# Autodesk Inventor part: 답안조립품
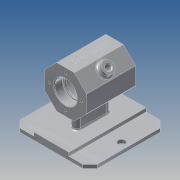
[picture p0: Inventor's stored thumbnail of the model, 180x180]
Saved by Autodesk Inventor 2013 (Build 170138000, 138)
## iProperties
Created: 2018-06
Part Number: 답안조립품
Material: 알루미늄 6061
Document SubType Name: Modeling
Designer: doa
Density: 2.71 g/cm^3
Mass: 554.043 g
Surface Area: 601.93 cm^2
Volume: 204.444 cm^3
Author: doa
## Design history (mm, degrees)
sketch "스케치2"
  geometry: L1 (30, -12.426)-(12.426, -30); L2 (12.426, -30)-(-12.426, -30); L3 (-12.426, -30)-(-30, -12.426); L4 (-30, -12.426)-(-30, 12.426); L5 (-30, 12.426)-(-12.426, 30); L6 (-12.426, 30)-(12.426, 30); L7 (12.426, 30)-(30, 12.426); L8 (30, 12.426)-(30, -12.426); 2 further points
  constraints: 16 end point, 1 coincident, 1 vertical, 17 other
  dimensions: "d7" = 60 distance between parallel lines of L6 L2
extrude "돌출1" new body sketch "스케치2" stored distance "d8" = 70; taper "d9" = 0 deg
sketch "스케치3"
  geometry: L1 (0, 35)-(0, -40.032); L2 (30, -35)-(-30, -35) reference; L3 (-30, -35)-(-30, 35) reference; L4 (-30, 35)-(30, 35) reference; L5 (30, 35)-(30, -35) reference; L6 (16, 35)-(16, 23); L7 (16, 23)-(14, 23); L8 (14, 23)-(14, 20); L9 (14, 20)-(25, 20); L10 (25, 20)-(25, -20); L11 (25, -20)-(14, -20); L12 (14, -20)-(14, -23); L13 (14, -23)-(16, -23); L14 (16, -23)-(16, -35); L15 (0, -35)-(16, -35); L16 (16, 35)-(0, 35); L17 (0, 35)-(0, -35); 1 further point
  constraints: 26 end point, 7 parallel, 3 perpendicular, 3 point on line, 2 collinear, 1 midpoint, 1 vertical
  dimensions: "d10" = 12 distance of L6.start L6.end; "d12" = 32 diameter of L6 L1; "d13" = 50 diameter of L10 L1; "d14" = 3 distance of L7.end L8.end; "d15" = 3 distance of L11.end L12.end; "d16" = 12 distance of L13.end L14.end; "d17" = 28 diameter of L8 L1; "d18" = 32 diameter of L14 L1; "d19" = 28 diameter of L12 L1
revolve "회전1" sketch "스케치3" stored, may be unused: angle "d20" = 90 deg
node "작업 평면1"
sketch "스케치5"
  geometry: L1 (-55, 55)-(55, 55); L2 (55, 55)-(55, -55); L3 (55, -55)-(-55, -55); L4 (-55, -55)-(-55, 55); 1 further point
  constraints: 8 end point, 2 parallel, 1 horizontal, 1 perpendicular
  dimensions: "d22" = 110 distance between parallel lines of L2 L4; "d24" = 110 distance between parallel lines of L3 L1; "d25" = 55 horizontal distance of L1.end point (0, 0); "d26" = 55 horizontal distance of L1.end point (0, 0)
extrude "돌출2" join sketch "스케치5" distance "d27" = 5; taper "d28" = 0 deg
sketch "스케치6"
  geometry: L1 (55, -55)-(55, 55) reference; L2 (55, -55)-(-55, -55) reference; L3 (-55, -55)-(-55, 55) reference; L4 (-55, 55)-(55, 55) reference; L5 (55, 55)-(55, -55) reference; L6 (55, -55)-(-55, -55) reference; L7 (-55, -55)-(-55, 55) reference; L8 (-55, 55)-(55, 55) reference; L9 (55, 55)-(55, -55) reference; L10 (-45, 55)-(-55, 45); L11 (-55, 55)-(-45, 55); L12 (-55, 55)-(-55, 45); L13 (45, 55)-(55, 55); L14 (55, 55)-(55, 45); L15 (55, 45)-(45, 55); L16 (45, -55)-(55, -45); L17 (55, -45)-(55, -55); L18 (55, -55)-(45, -55); L19 (-55, -55)-(-55, -45); L20 (-55, -45)-(-45, -55); L21 (-45, -55)-(-55, -55); 1 further point
  constraints: 24 end point, 8 point on line, 4 collinear, 3 perpendicular
  dimensions: "d29" = 10 distance of L3.end L10.end; "d30" = 10 distance of L3.end L10.start; "d31" = 10 distance of L2.end L19.end; "d32" = 10 distance of L20.end L2.end; "d33" = 10 distance of L1.start L16.start; "d34" = 10 distance of L16.end L1.start; "d35" = 10 distance of L1.end L13.start
extrude "돌출3" cut sketch "스케치6" stored distance "d36" = 5; taper "d37" = 0 deg
sketch "스케치7"
  geometry: L1 (-55, 45)-(-55, -45) reference; L2 (-45, -55)-(45, -55) reference; L3 (55, -45)-(55, 45) reference; L4 (45, 55)-(-45, 55) reference; L5 (25, 55)-(-25, 55); L6 (-25, 55)-(-25, -55); L7 (-25, -55)-(25, -55); L8 (25, -55)-(25, 55); 1 further point
  constraints: 8 end point, 2 parallel, 2 point on line, 1 horizontal, 1 perpendicular
  dimensions: "d38" = 30 distance between parallel lines of L3 L8; "d39" = 30 distance between parallel lines of L1 L6
extrude "돌출4" join sketch "스케치7" distance "d40" = 5; taper "d41" = 0 deg
sketch "스케치8"
  geometry: L1 (-25, 55)-(-25, -55) reference; L2 (5, 19)-(5, -19); L3 (-5, -19)-(-5, 19); A1 r 5 centre (0, 19) between (5, 19) and (-5, 19); A2 r 5 centre (0, -19) between (-5, -19) and (5, -19); 1 further point
  constraints: 4 end point, 4 point on circle, 3 tangent, 2 centre point, 2 vertical alignment, 1 equal radius, 1 parallel
  dimensions: "d42" = 10 diameter of A1; "d44" = 38 distance of A2.centre A1.centre; "d45" = 19 distance of point (0, 0) A1.centre
extrude "돌출5" join sketch "스케치8" stored distance "d46" = 5; taper "d47" = 0 deg
sketch "스케치9"
  geometry: L1 (0, 0)-(0, 70) reference; L2 (-24.853, 70)-(0, 70) reference; L3 (-24.853, 70)-(-24.853, 0) reference; L4 (0, 0)-(-24.853, 0) reference; L5 (-24.853, 35)-(0, 35); L6 (-12.426, 70)-(-12.426, 0); C1 r 8 at (-12.426, 35); 1 further point
  constraints: 4 end point, 4 midpoint, 1 centre point, 1 coincident
  dimensions: "d51" = 16 diameter of C1
extrude "돌출6" join sketch "스케치9" distance "d53" = 7; taper "d54" = 0 deg
sketch "스케치10"
  geometry: C1 r 8 at (0, 0) reference; C2 r 4 at (0, 0)
  constraints: 1 centre point, 1 coincident
  dimensions: "d55" = 8 diameter of C2
extrude "돌출7" cut sketch "스케치10" stored distance "d57" = 7; taper "d58" = 0 deg
fillet "모깎기1" dims "d59" = 1
sketch "스케치11"
  geometry: C1 r 16 at (0, 0) reference; A1 r 23 centre (0, 0) between (-23, 0) and (23, 0); 2 further points
  constraints: 4 point on circle, 2 horizontal alignment, 2 vertical alignment, 1 centre point, 1 coincident
  dimensions: "d60" = 46 diameter of A1
hole "구멍1" sketch "스케치11" at (-23, 0), (23, 0), (0, 23), (0, -23) diameter "d62" = 3.242; stored, may be unused: countersink angle "d66" = 90 deg, drill point angle "d68" = 118 deg; dims "d63" = 8, "d64" = 4, "d65" = 2, "d67" = 10
sketch "스케치12"
  geometry: L1 (-25, 55)-(-45, 55) reference; L2 (-55, 45)-(-55, -45) reference; C1 r 5 at (-45, 0); 1 further point
  constraints: 1 centre point
  dimensions: "d69" = 55 distance from line of C1.centre L1; "d70" = 10 distance from line of L2 C1.centre; "d71" = 10 diameter of C1
extrude "돌출8" cut sketch "스케치12" stored distance "d72" = 7; taper "d73" = 0 deg
fillet "모깎기2" dims "d74" = 2
fillet "모깎기3" dims "d75" = 3
fillet "모깎기4" dims "d76" = 0.3
fillet "모깎기5" dims "d77" = 2
fillet "모깎기6" dims "d78" = 3
chamfer "모따기1" distance "d79" = 1; stored, may be unused: second distance "d80" = 2, angle "d81" = 45 deg
sketch "스케치13"
  geometry: L1 (-24.024, 70)-(0, 70) reference; L2 (0, 70)-(0, 0) reference; L3 (0, 0)-(-24.024, 0) reference; L4 (-24.024, 0)-(-24.024, 70) reference; L5 (-34.338, 29.122)-(-34.338, 40.878) reference; L6 (17.988, 0)-(17.988, 70) reference; L7 (17.695, 70)-(17.695, 0) reference; L8 (0.707, 70)-(17.695, 70) reference; 3 further points; 1 other entity
  constraints: 1 coincident, 2 other
feature "엠보싱1" sketch "스케치13" dims "d7" = 60, "d82" = 0.5, "d83" = 0
chamfer "모따기2" distance "d84" = 1; stored, may be unused: second distance "d85" = 2, angle "d86" = 45 deg
node "솔리드1"
mirror "대칭1"
mirror "대칭2"
node "절단 모서리 투영1"
node "절단 모서리 투영2"
node "절단 모서리 투영3"
node "절단 모서리 투영4"
other parameters: "d21" = 62
